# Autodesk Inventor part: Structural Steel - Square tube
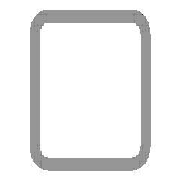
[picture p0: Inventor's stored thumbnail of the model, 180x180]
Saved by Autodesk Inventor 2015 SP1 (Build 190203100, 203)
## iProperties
_CCFamilyMember: 2
_CCFamilyDisplayName: ISO 4019 (Square) - Structural steels - Cold-formed, welded, structural hollow sections
_FrameMemberDoc: Frame Member File
_Version: 15.0.0
_GetPNFromCC: 1
Created: 2011-06
Part Number: Structural Steel - Square tube
Material: Stainless Steel
Document SubType Name: Modeling
Standard: ISO
Designer: Guilherme Augusto Franco de Souza
Standard Revision: Second edition 2001-09-01
Standards Organization: ISO
Language: en-US
Size Designation: 25x25x2
Categories: <MemberInstance><Categories><Category DisplayName="Structural Shapes" InternalName="089c4875-fa83-4c05-b084-43b9cc11f5ed" Mnemonic="GRDR"><CategoryParameter Dis
Stock Number: 25x25x2
Density: 8.08 g/cm^3
Description: ISO 4019 - 25x25x2
Appearance: Steel
G_L: 325,000 mm
G_W: 25,000 mm
G_H: 25,000 mm
+AFD0FFE8-64BD-4334-BDAE-4CE3C98D6953+CUTDETAIL1: Cut
+F6BDAD85-E222-4261-9D7A-C9B2A77C0AB9+CUTDETAIL2: Cut
IsCustomPart: 1
Author: Guilherme Augusto Franco de Souza
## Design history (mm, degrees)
node "Start plane"
node "End plane"
sketch "Sketch"
  geometry: L1 (-12.5, -8.5)-(-12.5, 8.5); L2 (-8.5, 12.5)-(8.5, 12.5); L3 (12.5, 8.5)-(12.5, -8.5); L4 (8.5, -12.5)-(-8.5, -12.5); L5 (-8.5, 10.5)-(8.5, 10.5); L6 (10.5, 8.5)-(10.5, -8.5); L7 (8.5, -10.5)-(-8.5, -10.5); L8 (-10.5, -8.5)-(-10.5, 8.5); L9 (0, 18.66)-(0, -18.66) reference; L10 (-18.66, 0)-(18.66, 0) reference; A1 r 4 centre (-8.5, -8.5) between (-12.5, -8.5) and (-8.5, -12.5); A2 r 4 centre (8.5, 8.5) between (12.5, 8.5) and (8.5, 12.5); A3 r 4 centre (-8.5, 8.5) between (-8.5, 12.5) and (-12.5, 8.5); A4 r 4 centre (8.5, -8.5) between (8.5, -12.5) and (12.5, -8.5); A5 r 2 centre (-8.5, 8.5) between (-8.5, 10.5) and (-10.5, 8.5); A6 r 2 centre (8.5, 8.5) between (10.5, 8.5) and (8.5, 10.5); A7 r 2 centre (8.5, -8.5) between (8.5, -10.5) and (10.5, -8.5); A8 r 2 centre (-8.5, -8.5) between (-10.5, -8.5) and (-8.5, -10.5)
  constraints: 16 end point, 16 point on circle, 8 centre point, 8 tangent, 4 parallel, 3 equal radius, 2 perpendicular, 7 other
  dimensions: "d7" = 4 radius of A1 (= G_IR); "d9" = 25 distance between parallel lines of L1 L3 (= G_W); "d11" = 25 distance between parallel lines of L2 L4 (= G_H); "d12" = 2 distance between parallel lines of L3 L6 (= G_T); "d15" = 12.5 distance between parallel lines of L9 L3 (= 0.5 x d9); "d16" = 12.5 distance between parallel lines of L2 L10 (= 0.5 x d11)
extrude "Body" new body sketch "Sketch" stored distance "d3" = 325 (= G_L); taper "d4" = 0 deg
node "Driven Length"
  sketch "Sketch3"
    geometry: L1 (0, 0)-(10, 0) reference
    constraints: 2 end point, 1 horizontal
  workplane "Work Plane3"
  sketch "Sketch4"
    geometry: L1 (-2, 25)-(12, 25) reference; L2 (-2, 300)-(12, 300) reference
    dimensions: "d18" = 275 distance between parallel lines of L1 L2 (derived)
workplane "Work Plane4"
split "Split1" sketch "Sketch"
workplane "Work Plane5"
split "Split2" sketch "Sketch"
body "Solid1"
other parameters: "G_W" = 25 [user parameter; used in 1 equation term], "G_H" = 25 [user parameter; used in 1 equation term], "G_T" = 2 [user parameter; used in 1 equation term], "G_IR" = 4 [user parameter; used in 1 equation term], "G_L" = 325 [user parameter; used in 1 equation term], "G_OFFSET_START" = -25 [user parameter; used in 1 equation term], "G_OFFSET_END" = -25 [user parameter; used in 1 equation term], "d13" = 25 (= -G_OFFSET_START), "d14" = 300 (= G_OFFSET_END + B_L), "B_L" = 325 [user parameter; used in 1 equation term], "d17" = 90 deg, "MAS" = 0.136 [user parameter]
